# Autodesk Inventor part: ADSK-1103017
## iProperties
Shininess: 50.0
Length Units: 11272
Angle Units: 11279
Time Units: 11290
Mass Units: 11286
Length Display Precision: 4
Angle Display Precision: 2
Compacted: True
Created: 2000-09
Part Number: ADSK-1103017
Document SubType Name: Modeling
Description: AIR INTAKE
Mass: 0.433217 g
Surface Area: 3.22275 cm^2
Volume: 0.159859 cm^3
Density: 2.71 g/cm^3
Material: Aluminum-6061
Density: 0.0
Volumn: 0.0
Area: 0.0
PropertySet Name: Model Information
Control State: 0
Master: False
Checked Out: False
Author: Autodesk, Inc.
